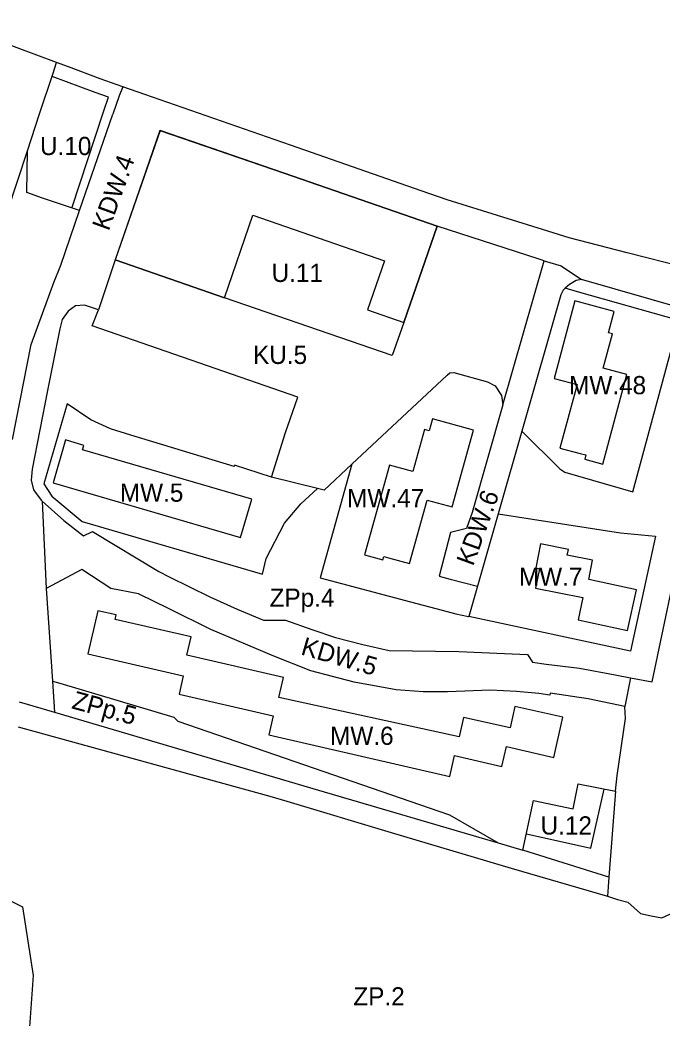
# Model space of a CAD drawing. Extents: x 7424434 to 7425898, y 5541432 to 5542659.
# Drawn here: x 7424993.9 to 7425170.3, y 5542089.1 to 5542363.2 of the extents above; entities that cross this region are included whole.
import ezdxf

# ---------------------------------------------------------------- set-up
doc = ezdxf.new("R2010")
doc.units = 0
for name, color, linetype in [('linie rozgraniczające', 7, 'Continuous'), ('nieprzekraczalne linie zabudowy', 7, 'Continuous'), ('obowiazujace linie zabudowy', 7, 'Continuous'), ('przeznaczenia terenów', 7, 'Continuous')]:
    doc.layers.add(name, color=color, linetype=linetype)

msp = doc.modelspace()

# ---------------------------------------------------------------- linework, layer by layer
at = {"layer": 'linie rozgraniczające'}
for p, q in [((7425004.03, 5542351.55), (7424972.7, 5542363.24)), ((7425002.97, 5542348.36), (7425004.03, 5542351.55)), ((7425007.3, 5542350.33), (7425004.03, 5542351.55)), ((7425015.98, 5542347.09), (7425007.3, 5542350.33)), ((7424999.36, 5542337.45), (7425002.97, 5542348.36)), ((7425022.24, 5542344.9), (7425015.98, 5542347.09)), ((7425022.24, 5542344.9), (7425021.21, 5542342.41)), ((7425028.24, 5542342.8), (7425022.24, 5542344.9)), ((7425021.21, 5542342.41), (7425019.47, 5542337.39)), ((7425068.29, 5542328.83), (7425028.24, 5542342.8)), ((7424995.99, 5542327.25), (7424999.36, 5542337.45)), ((7425010.26, 5542310.87), (7425019.47, 5542337.39)), ((7425032.42, 5542332.9), (7425027.63, 5542319.06)), ((7425032.42, 5542332.9), (7425066.53, 5542321.14)), ((7425104.14, 5542316.31), (7425068.29, 5542328.83)), ((7424982.33, 5542285.97), (7424995.99, 5542327.25)), ((7424995.85, 5542315.82), (7424995.99, 5542327.25)), ((7425066.53, 5542321.14), (7425108.57, 5542306.63)), ((7425027.63, 5542319.06), (7425020.12, 5542297.36)), ((7425000.17, 5542314.33), (7424995.85, 5542315.82)), ((7425010.26, 5542310.87), (7425000.17, 5542314.33)), ((7425111.3, 5542313.81), (7425104.14, 5542316.31)), ((7425138.96, 5542305.19), (7425111.3, 5542313.81)), ((7425005.2, 5542295.91), (7425010.26, 5542310.87)), ((7425108.57, 5542306.63), (7425099.37, 5542280.16)), ((7425136.59, 5542297.55), (7425108.57, 5542306.63)), ((7425144.82, 5542303.37), (7425138.96, 5542305.19)), ((7425160.74, 5542299.31), (7425144.82, 5542303.37)), ((7425183.57, 5542293.49), (7425160.74, 5542299.31)), ((7425003.26, 5542291.13), (7425005.2, 5542295.91)), ((7425020.12, 5542297.36), (7425015.51, 5542283.63)), ((7425050.16, 5542286.96), (7425020.12, 5542297.36)), ((7425126.65, 5542257.57), (7425138, 5542297.11)), ((7425138, 5542297.11), (7425136.59, 5542297.55)), ((7425138, 5542297.11), (7425142.64, 5542295.67)), ((7425142.64, 5542295.67), (7425148.18, 5542291.98)), ((7424997.06, 5542274.09), (7425003.26, 5542291.13)), ((7425143.74, 5542289.53), (7425143.21, 5542289.02)), ((7425144.88, 5542290.61), (7425143.74, 5542289.53)), ((7425147.13, 5542288.57), (7425143.74, 5542289.53)), ((7425146.75, 5542291.66), (7425144.88, 5542290.61)), ((7425148.18, 5542291.98), (7425146.75, 5542291.66)), ((7425184.45, 5542281.48), (7425148.18, 5542291.98)), ((7425096.2, 5542271.04), (7425050.16, 5542286.96)), ((7425142.55, 5542287.7), (7425131.81, 5542250.29)), ((7425143.21, 5542289.02), (7425142.55, 5542287.7)), ((7425175.09, 5542280.69), (7425147.13, 5542288.57)), ((7425009.23, 5542284.73), (7425007.22, 5542283.28)), ((7425011.66, 5542284.88), (7425009.23, 5542284.73)), ((7425015.51, 5542283.63), (7425011.66, 5542284.88)), ((7425007.22, 5542283.28), (7425005.58, 5542280.96)), ((7425013.83, 5542279.19), (7425015.51, 5542283.63)), ((7425005.58, 5542280.96), (7425004.86, 5542278.36)), ((7425070.27, 5542259.63), (7425013.83, 5542279.19)), ((7425099.37, 5542280.16), (7425096.2, 5542271.04)), ((7425162.36, 5542233.68), (7425175.09, 5542280.69)), ((7425004.86, 5542278.36), (7425001.47, 5542261.46)), ((7424991.92, 5542247.99), (7424997.06, 5542274.09)), ((7425085.12, 5542241.2), (7425111.31, 5542265.72)), ((7425111.31, 5542265.72), (7425112.05, 5542266.32)), ((7425112.05, 5542266.32), (7425113.13, 5542266.38)), ((7425113.13, 5542266.38), (7425122.4, 5542263.88)), ((7425122.4, 5542263.88), (7425124.54, 5542262.71)), ((7425124.54, 5542262.71), (7425126.22, 5542260.12)), ((7425001.47, 5542261.46), (7424997.34, 5542239.85)), ((7425066.89, 5542249.89), (7425070.27, 5542259.63)), ((7425126.22, 5542260.12), (7425126.65, 5542257.57)), ((7425006.95, 5542257.77), (7425000.55, 5542235.79)), ((7425013.46, 5542253.39), (7425006.95, 5542257.77)), ((7425126.65, 5542257.57), (7425118.14, 5542227.96)), ((7425018.81, 5542250.91), (7425013.46, 5542253.39)), ((7425024.41, 5542249.18), (7425018.81, 5542250.91)), ((7425052.83, 5542240.6), (7425024.41, 5542249.18)), ((7425063.01, 5542237.69), (7425066.89, 5542249.89)), ((7425131.81, 5542250.29), (7425125.84, 5542229.48)), ((7425131.81, 5542250.29), (7425142.3, 5542239.93)), ((7425052.92, 5542240.96), (7425052.83, 5542240.6)), ((7425063.01, 5542237.69), (7425052.92, 5542240.96)), ((7425085.12, 5542241.2), (7425076.46, 5542210.02)), ((7425085.12, 5542241.2), (7425077.49, 5542234.06)), ((7424997.34, 5542239.85), (7424997.04, 5542236.82)), ((7425075.67, 5542234.55), (7425063.01, 5542237.69)), ((7425142.3, 5542239.93), (7425143.64, 5542239.03)), ((7425143.64, 5542239.03), (7425162.36, 5542233.68)), ((7424997.04, 5542236.82), (7424997.63, 5542234.19)), ((7425000.55, 5542235.79), (7425002.66, 5542232.42)), ((7424997.63, 5542234.19), (7424999.76, 5542231.32)), ((7425002.66, 5542232.42), (7425011, 5542225.48)), ((7425071.11, 5542230.3), (7425075.67, 5542234.55)), ((7425077.49, 5542234.06), (7425075.67, 5542234.55)), ((7424999.76, 5542231.32), (7425000.07, 5542231.04)), ((7425000.07, 5542231.04), (7425001.18, 5542207.08)), ((7425000.07, 5542231.04), (7425005.99, 5542225.8)), ((7425066.6, 5542225.07), (7425071.11, 5542230.3)), ((7425125.84, 5542229.48), (7425125.29, 5542227.58)), ((7425118.14, 5542227.96), (7425116.61, 5542223.59)), ((7425125.29, 5542227.58), (7425119.61, 5542207.75)), ((7425125.29, 5542227.58), (7425158.94, 5542222.37)), ((7425005.99, 5542225.8), (7425011.37, 5542221.58)), ((7425011, 5542225.48), (7425060.56, 5542211.03)), ((7425061.55, 5542215.34), (7425066.6, 5542225.07)), ((7425011.37, 5542221.58), (7425013.92, 5542222.74)), ((7425013.92, 5542222.74), (7425032.1, 5542211.8)), ((7425112.27, 5542222.47), (7425109.09, 5542210.43)), ((7425116.61, 5542223.59), (7425112.27, 5542222.47)), ((7425158.94, 5542222.37), (7425168.51, 5542221.47)), ((7425168.51, 5542221.47), (7425161.7, 5542189.84)), ((7425167.64, 5542181.41), (7425176.32, 5542222.8)), ((7425060.56, 5542211.03), (7425061.55, 5542215.34)), ((7425010.94, 5542212.32), (7425001.18, 5542207.08)), ((7425018.92, 5542207.09), (7425010.94, 5542212.32)), ((7425032.1, 5542211.8), (7425034.94, 5542210.28)), ((7425034.94, 5542210.28), (7425046.08, 5542204.8)), ((7425076.46, 5542210.02), (7425101.27, 5542203.42)), ((7425109.09, 5542210.43), (7425112.17, 5542209.65)), ((7425112.17, 5542209.65), (7425119.61, 5542207.75)), ((7425119.61, 5542207.75), (7425117.22, 5542199.36)), ((7425001.18, 5542207.08), (7425002.9, 5542181.66)), ((7425026.53, 5542205.58), (7425018.92, 5542207.09)), ((7425034.93, 5542201.48), (7425026.53, 5542205.58)), ((7425046.08, 5542204.8), (7425053.64, 5542201.39)), ((7425101.27, 5542203.42), (7425109.95, 5542201.11)), ((7425046.36, 5542195.86), (7425034.93, 5542201.48)), ((7425053.64, 5542201.39), (7425060.88, 5542198.4)), ((7425109.95, 5542201.11), (7425113.7, 5542200.11)), ((7425113.7, 5542200.11), (7425117.2, 5542199.36)), ((7425117.2, 5542199.36), (7425117.22, 5542199.36)), ((7425161.7, 5542189.84), (7425117.22, 5542199.36)), ((7425060.88, 5542198.4), (7425066.92, 5542198.39)), ((7425066.92, 5542198.39), (7425074.17, 5542195.86)), ((7425063.72, 5542188.5), (7425046.36, 5542195.86)), ((7425074.17, 5542195.86), (7425080.6, 5542193.66)), ((7425080.6, 5542193.66), (7425088.19, 5542191.68)), ((7425088.19, 5542191.68), (7425095.37, 5542190.1)), ((7425073.87, 5542184.5), (7425063.72, 5542188.5)), ((7425095.37, 5542190.1), (7425114.5, 5542189.81)), ((7425114.5, 5542189.81), (7425133.37, 5542189)), ((7425133.37, 5542189), (7425134.78, 5542186.83)), ((7425134.78, 5542186.83), (7425138.49, 5542186.28)), ((7425138.49, 5542186.28), (7425147.69, 5542185.22)), ((7425085.76, 5542181.37), (7425073.87, 5542184.5)), ((7425147.69, 5542185.22), (7425157.51, 5542183.4)), ((7425157.51, 5542183.4), (7425161.67, 5542182.58)), ((7425002.9, 5542181.66), (7425004.9, 5542181.07)), ((7425002.9, 5542181.66), (7425003.48, 5542173.11)), ((7425004.9, 5542181.07), (7425036.22, 5542171.75)), ((7425097.32, 5542179.21), (7425085.76, 5542181.37)), ((7425161.67, 5542182.58), (7425160.12, 5542174.7)), ((7425161.67, 5542182.58), (7425167.64, 5542181.41)), ((7425104.75, 5542178.69), (7425097.32, 5542179.21)), ((7425111.38, 5542178.68), (7425104.75, 5542178.69)), ((7425123.23, 5542179.17), (7425111.38, 5542178.68)), ((7425130.35, 5542178.81), (7425123.23, 5542179.17)), ((7425136.46, 5542178.21), (7425130.35, 5542178.81)), ((7425139.53, 5542177.82), (7425136.46, 5542178.21)), ((7425139.64, 5542178.38), (7425139.53, 5542177.82)), ((7425150.07, 5542176.78), (7425139.64, 5542178.38)), ((7424993.72, 5542175.99), (7425003.48, 5542173.11)), ((7425160.12, 5542174.7), (7425150.07, 5542176.78)), ((7425160.35, 5542171.34), (7425160.12, 5542174.7)), ((7425003.48, 5542173.11), (7425075.95, 5542151.7)), ((7425036.22, 5542171.75), (7425037.28, 5542170.61)), ((7424993.48, 5542169.09), (7424995.11, 5542168.64)), ((7425037.28, 5542170.61), (7425111.97, 5542144.9)), ((7425157.99, 5542155.77), (7425160.35, 5542171.34)), ((7424995.11, 5542168.64), (7424997.76, 5542167.91)), ((7424997.76, 5542167.91), (7425062.56, 5542150.02)), ((7425157.55, 5542151.38), (7425157.99, 5542155.77)), ((7425145.92, 5542146.58), (7425147.29, 5542153.45)), ((7425147.29, 5542153.45), (7425157.55, 5542151.38)), ((7425062.56, 5542150.02), (7425067.31, 5542148.71)), ((7425075.95, 5542151.7), (7425125.28, 5542137.26)), ((7425157.55, 5542151.38), (7425155.73, 5542127.84)), ((7424937.56, 5542147.46), (7424994.63, 5542119.66)), ((7425067.31, 5542148.71), (7425095.96, 5542140.11)), ((7425132.11, 5542135.26), (7425135.06, 5542148.82)), ((7425135.06, 5542148.82), (7425145.92, 5542146.58)), ((7425111.97, 5542144.9), (7425125.28, 5542137.26)), ((7425095.96, 5542140.11), (7425128.87, 5542130.23)), ((7425125.28, 5542137.26), (7425132.11, 5542135.26)), ((7425155.73, 5542127.84), (7425132.11, 5542135.26)), ((7425128.87, 5542130.23), (7425155.32, 5542122.54)), ((7425155.73, 5542127.84), (7425155.53, 5542125.19)), ((7425155.53, 5542125.19), (7425155.32, 5542122.54)), ((7425155.32, 5542122.54), (7425158.15, 5542121.71)), ((7424994.63, 5542119.66), (7424997.54, 5542100.77)), ((7425158.15, 5542121.71), (7425160.98, 5542120.89)), ((7425160.98, 5542120.89), (7425162.73, 5542119.35)), ((7425162.73, 5542119.35), (7425164.47, 5542117.8)), ((7425164.47, 5542117.8), (7425167.38, 5542117.21)), ((7425167.38, 5542117.21), (7425170.29, 5542116.62)), ((7425170.29, 5542116.62), (7425174.64, 5542118.61)), ((7424997.54, 5542100.77), (7424993.13, 5542039.11))]:
    msp.add_line(p, q, dxfattribs=at)
at = {"layer": 'nieprzekraczalne linie zabudowy'}
for points in [[(7425008.17, 5542311.59), (7425016.93, 5542338.01), (7425018.27, 5542342.05), (7425014.62, 5542343.33), (7425002.77, 5542347.75)], [(7425133.08, 5542139.73), (7425150.8, 5542135.76), (7425154.44, 5542152.01)]]:
    msp.add_lwpolyline(points, dxfattribs=at)
at = {"layer": 'obowiazujace linie zabudowy'}
for points in [[(7425020.12, 5542297.35), (7425050.16, 5542286.96), (7425057.97, 5542309.59), (7425094.13, 5542297.12), (7425089.46, 5542283.6), (7425099.37, 5542280.16), (7425108.57, 5542306.63), (7425066.53, 5542321.13), (7425032.43, 5542332.9)], [(7425160.71, 5542265.85), (7425154.18, 5542267.62), (7425156.72, 5542277.01), (7425155.63, 5542277.3), (7425157.21, 5542283.15), (7425146.42, 5542286.06), (7425140.67, 5542264.81), (7425147.04, 5542263.09), (7425142.31, 5542245.61), (7425147.81, 5542244.12), (7425149.44, 5542243.76), (7425149.12, 5542242.59), (7425154.05, 5542241.25)], [(7425101.01, 5542213.91), (7425105.86, 5542231.39), (7425112.66, 5542229.5), (7425118.51, 5542250.58), (7425107.28, 5542253.71), (7425106.35, 5542250.36), (7425105.08, 5542250.72), (7425101.89, 5542239.21), (7425095.44, 5542241), (7425088.59, 5542216.32), (7425093.61, 5542214.92), (7425093.88, 5542215.89), (7425095.18, 5542215.53)], [(7425054.56, 5542221.11), (7425057.62, 5542231.6), (7425011.15, 5542245.16), (7425011.52, 5542246.4), (7425006.46, 5542247.88), (7425003.04, 5542236.14)], [(7425163.29, 5542206.73), (7425150.22, 5542209.54), (7425151.27, 5542214.88), (7425144.3, 5542216.26), (7425144.62, 5542217.84), (7425136.94, 5542219.36), (7425135.63, 5542212.73), (7425136.65, 5542212.53), (7425135.59, 5542207.16), (7425148.55, 5542204.6), (7425147.34, 5542198.49), (7425160.89, 5542195.58)], [(7425143.1, 5542171.79), (7425129.93, 5542174.69), (7425128.64, 5542168.81), (7425115.76, 5542171.62), (7425114.61, 5542166.36), (7425065.05, 5542177.16), (7425066.31, 5542182.66), (7425039.78, 5542188.75), (7425040.95, 5542193.82), (7425020.12, 5542198.61), (7425020.4, 5542199.81), (7425015.34, 5542200.97), (7425012.62, 5542189.14), (7425038.81, 5542183.11), (7425037.66, 5542178.09), (7425063.5, 5542172.15), (7425062.29, 5542166.9), (7425112.04, 5542155.47), (7425113.36, 5542161.19), (7425126.32, 5542158.21), (7425127.57, 5542163.67), (7425140.64, 5542160.67)]]:
    msp.add_lwpolyline(points, close=True, dxfattribs=at)

# ---------------------------------------------------------------- texts
at = {"layer": 'przeznaczenia terenów'}
for s, p in [('U.10', (7424999.45, 5542326.13)), ('U.11', (7425063.08, 5542291.28)), ('KU.5', (7425057.98, 5542268.76)), ('MW.48', (7425144.8, 5542260.44)), ('MW.5', (7425021.39, 5542230.92)), ('MW.47', (7425083.82, 5542229.41)), ('MW.7', (7425131.02, 5542207.84)), ('ZPp.4', (7425062.53, 5542202.07)), ('MW.6', (7425079.14, 5542164.13)), ('U.12', (7425136.97, 5542139.51)), ('ZP.2', (7425085.53, 5542092.57))]:
    msp.add_text(s, height=5, dxfattribs=at).set_placement(p)
for s, rotation, p in [('KDW.4', 70, (7425018.32, 5542305.08)), ('KDW.6', 70, (7425118.43, 5542213.03)), ('KDW.5', 343.6956, (7425070.86, 5542189.03)), ('ZPp.5', 344.9035, (7425007.91, 5542174.2))]:
    msp.add_text(s, height=5, rotation=rotation, dxfattribs=at).set_placement(p)

doc.saveas('drawing.dxf')
